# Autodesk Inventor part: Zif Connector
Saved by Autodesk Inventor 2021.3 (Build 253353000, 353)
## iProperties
Created: 2023-02
Part Number: Zif Connector
Material: Generic
Document SubType Name: Modeling
Designer: AdminForWorker
Density: 1 g/cm^3
Appearance: Default
Title: Zif Connector
Author: AdminForWorker
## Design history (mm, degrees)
feature "Body1"
body "Solid1"
